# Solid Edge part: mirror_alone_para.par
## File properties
Author: Haley
Template: Metric Part.par
Last saved by: Lee
Revision: 11
Application: Solid Edge
Accuracy: 0.990
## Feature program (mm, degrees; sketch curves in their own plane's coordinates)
sketch for "unnamed RevolvedProtrusion 1" plane through (0, 0, 0) normal (0, -1, 0) x-axis (1, 0, 0)
  line (450, 92.05) -> (450, -50)
  line (0, -50) -> (450, -50)
  line (0, 0) -> (0, -50)
revolve "unnamed RevolvedProtrusion 1" add finite 360 deg
sketch for "unnamed Cutout 1" plane through (0, 0, -50) normal (0, 0, -1) x-axis (0, 1, 0)
  line (-300, -275) -> (300, -275)
  line (300, -275) -> (300, 275)
  line (300, 275) -> (-300, 275)
  line (-300, 275) -> (-300, -275)
extrude "unnamed Cutout 1" cut through along -normal
sketch for "unnamed RevolvedCutout 1" plane through (0, 0, 0) normal (0, -1, 0) x-axis (1, 0, 0)
  line (451.0311, -50) -> (0, -50)
  line (451.0311, 89.2328) -> (451.0311, -50)
  line (0, -3) -> (0, -50)
revolve "unnamed RevolvedCutout 1" cut full turn 360 deg
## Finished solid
Body 1: solid body, 6 faces, 12 edges, 8 vertices.
  Faces by surface: plane 4, spun 2
  Edges by curve: intersection 8, line 4
Bounding box of the edges (mm; curved faces can reach further): 550.000 x 600.000 x 44.015, from (-275, -300, 31.4574) to (275, 300, 75.4727).
Planar faces by outward normal: +x 1, +y 1, -x 1, -y 1
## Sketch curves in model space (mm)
line (100, 0, 0) -> (150, 0, 0)
line (150, 0, 0) -> (200, 0, 0)
line (200, 0, 0) -> (250, 0, 0)
line (250, 0, 0) -> (300, 0, 0)
line (300, 0, 0) -> (350, 0, 0)
line (100, 0, 0) -> (100, 0, 4.55)
line (200, 0, 0) -> (200, 0, 18.18)
line (300, 0, 0) -> (300, 0, 40.91)
line (0, 0, 0) -> (0, 0, -100)
line (150, 0, 0) -> (150, 0, 10.23)
line (250, 0, 0) -> (250, 0, 28.41)
line (350, 0, 0) -> (350, 0, 55.68)
line (50, 0, 0) -> (50, 0, 1.14)
line (50, 0, 0) -> (100, 0, 0)
line (400, 0, 0) -> (400, 0, 72.73)
line (350, 0, 0) -> (400, 0, 0)
line (0, 0, 0) -> (0, 0, -50)
line (0, 0, -50) -> (450, 0, -50)
line (450, 0, 92.05) -> (450, 0, -50)
spline (0, 0, 0) -> (225.1206, 0, 22.8973) -> (450, 0, 92.05)
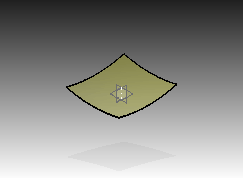
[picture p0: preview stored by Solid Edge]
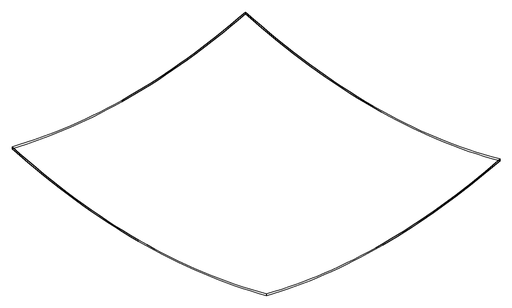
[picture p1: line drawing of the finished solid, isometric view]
